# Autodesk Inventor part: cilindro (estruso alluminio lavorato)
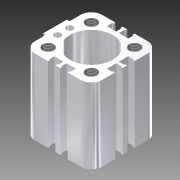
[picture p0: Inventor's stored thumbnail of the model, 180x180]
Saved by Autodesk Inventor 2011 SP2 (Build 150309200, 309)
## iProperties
Created: 2018-03
Part Number: cilindro (estruso alluminio lavorato)
Document SubType Name: Modeling
Designer: 18619647
Density: 1 g/cm^3
Author: 18619647
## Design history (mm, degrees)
sketch "Schizzo1"
  geometry: L1 (0, 0)-(25, 0); L2 (25, 0)-(25, 25); L3 (25, 25)-(-25, 25); L4 (-25, 25)-(-25, -25); L5 (-25, -25)-(25, -25); L6 (25, -25)-(25, 0); C1 r 15.75 at (0, 0); 1 further point
  constraints: 12 end point, 2 parallel, 2 perpendicular, 1 centre point, 1 coincident, 1 horizontal
  dimensions: "d0" = 31.5 diameter of C1; "d1" = 25 distance of L1.start L1.end; "d2" = 25 distance of L1.end L2.end; "d3" = 50 distance of L2.end L3.end; "d4" = 50 distance of L3.end L4.end; "d5" = 50 distance of L4.end L5.end
extrude "Estrusione1" new body sketch "Schizzo1" distance "d6" = 56; taper "d7" = 0 deg
fillet "Raccordo1" dims "d8" = 8
sketch "Schizzo2"
  geometry: L1 (-25, -17)-(-25, 17) reference; L2 (-17, 25)-(17, 25) reference; L3 (-25, 0)-(-27, 0); L4 (-27, 0)-(-27, -8.8); L5 (-27, -8.8)-(-25, -8.8); L6 (-25, -8.8)-(-25, 8.8); L7 (-25, 8.8)-(-27, 8.8); L8 (-27, 8.8)-(-27, 0)
  constraints: 12 end point, 2 parallel, 2 perpendicular, 2 point on line, 1 midpoint
  dimensions: "d9" = 2 distance of L3.start L3.end; "d10" = 8.8 distance of L3.end L4.end; "d11" = 2 distance of L4.end L5.end; "d12" = 17.6 distance of L5.end L6.end
extrude "Estrusione2" join sketch "Schizzo2" distance "d13" = 56; taper "d14" = 0 deg
hole "Hole1" diameter "d17" = 8.2; stored, may be unused: countersink angle "d21" = 82 deg, drill point angle "d23" = 118 deg; dims "d15" = 8.9, "d16" = 8.9, "d18" = 6, "d19" = 3.023, "d20" = 2, "d22" = 8.2
feature "Filettatura1" dims "d24" = 8, "d25" = 0
node "Piano di lavoro1"
sketch "Schizzo3"
  geometry: L1 (1.75, -25)-(1.75, -23.5); L2 (1.75, -23.5)-(1, -23.5); L3 (1, -23.5)-(1, -19.5); L4 (1, -19.5)-(8, -19.5); L5 (8, -19.5)-(8, -23.5); L6 (8, -23.5)-(7.25, -23.5); L7 (7.25, -23.5)-(7.25, -25); L8 (-1, -19.5)-(-8, -19.5); L9 (-1, -23.5)-(-1, -19.5); L10 (-1.75, -23.5)-(-1, -23.5); L11 (-1.75, -25)-(-1.75, -23.5); L12 (-8, -19.5)-(-8, -23.5); L13 (-8, -23.5)-(-7.25, -23.5); L14 (-7.25, -23.5)-(-7.25, -25); L15 (-17, 25)-(17, 25) reference; L16 (25, 17)-(25, 8.8) reference; L17 (25, 8.8)-(27, 8.8) reference; L18 (27, 8.8)-(27, -8.8) reference; L19 (27, -8.8)-(25, -8.8) reference; L20 (25, -8.8)-(25, -17) reference; L21 (17, -25)-(-17, -25) reference; L22 (-25, -17)-(-25, 17) reference; L23 (7.25, -25)-(1.75, -25); L24 (-1.75, -25)-(-7.25, -25); C1 r 4.1 at (16.1, -16.1) reference; C2 r 15.75 at (0, 0) reference; A1 r 8 centre (-17, 17) between (-17, 25) and (-25, 17) reference; A2 r 8 centre (17, 17) between (25, 17) and (17, 25) reference; A3 r 8 centre (17, -17) between (17, -25) and (25, -17) reference; A4 r 8 centre (-17, -17) between (-25, -17) and (-17, -25) reference
  constraints: 32 end point, 2 collinear, 1 parallel, 1 perpendicular
  dimensions: "d30" = 1.5 distance of L1.start L1.end; "d31" = 0.75 distance of L1.end L2.end; "d32" = 4 distance of L2.end L3.end; "d33" = 7 distance of L3.end L4.end; "d34" = 4 distance of L4.end L5.end; "d35" = 0.75 distance of L5.end L6.end
extrude "Estrusione3" cut sketch "Schizzo3" distance "d36" = 56; taper "d37" = 0 deg
pattern_circular "Serie circolare1" dims angle "d39" = 180 deg
pattern_linear "Serie rettangolare1" dims "d43" = 32.2, "d46" = 32.2
sketch "Schizzo4"
  geometry: L1 (7.25, 25)-(17, 25) reference; L2 (0, 0)-(20.5, 0); L3 (20.5, 0)-(20.5, 4.5); C1 r 15.75 at (0, 0) reference
  constraints: 4 end point, 1 parallel, 1 perpendicular
  dimensions: "d47" = 20.5 distance of L2.start L2.end; "d48" = 4.5 distance of L2.end L3.end
hole "Hole2" sketch "Schizzo4" at (20.5, 4.5) diameter "d49" = 5; stored, may be unused: countersink angle "d53" = 82 deg, drill point angle "d55" = 118 deg; dims "d50" = 6, "d51" = 3.023, "d52" = 2, "d54" = 8.2
mirror "Specchio1"
feature "Filettatura3" dims "d56" = 8, "d57" = 0
feature "Filettatura4" dims "d58" = 8, "d59" = 0
feature "Filettatura5" dims "d60" = 8, "d61" = 0
feature "Filettatura6" dims "d62" = 8, "d63" = 0
sketch "Schizzo5"
  geometry: C1 r 15.75 at (0, 0) reference; C2 r 16 at (0, 0)
  constraints: 1 centre point, 1 coincident
  dimensions: "d64" = 32 diameter of C2
extrude "Estrusione4" cut sketch "Schizzo5" stored distance "d65" = 0; taper "d66" = 0 deg
fillet "Raccordo2" dims "d67" = 0.5
node "Solido1"
node "Proietta spigoli di taglio1"
other parameters: "d28" = 28
